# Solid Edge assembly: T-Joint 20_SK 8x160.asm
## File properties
Author: fknapp
Template: iso metric assembly.asm
Last saved by: fknapp
Revision: 7
Application: Solid Edge
Username: fknapp
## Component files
Rundzylinderscheibe_8er_Schraube_45_V3.par
SK_Schraube_8x160.par
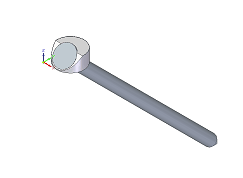
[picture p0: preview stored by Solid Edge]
